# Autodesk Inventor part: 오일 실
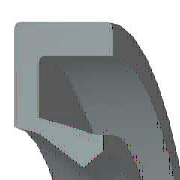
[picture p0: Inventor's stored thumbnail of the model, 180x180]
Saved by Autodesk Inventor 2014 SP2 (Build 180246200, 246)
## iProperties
IsCustomPart: 1
Created: 2012-02
Part Number: 오일 실
Material: 고무
Description: 오일 실 - 스프링 장착, 비스프링, 고무 덮개 G
Document SubType Name: Modeling
Standard: JIS B 2402
Designer: mduedu
Standards Organization: JIS
Language: ko-KR
Size Designation: 20 32 5 A
Categories: <MemberInstance><Categories><Category DisplayName="샤프트 부품" InternalName="7f7aeb1f-a693-4053-b835-cee3144e0d98" Mnemonic="SHFT"><Category DisplayName="실링" Intern
Density: 0.93 g/cm^3
Appearance: 고무 - 검은색 - 버전 1.1
Author: mduedu
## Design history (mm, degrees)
body "Solid1"
revolve "회전1" stored, may be unused: angle "d29" = 360 deg
chamfer "모따기1" distance "d30" = 0.25 (= 0.05 x b); stored, may be unused: second distance "d31" = 0.5 (= 0.1 x b), angle "d39" = 45 deg
chamfer "모따기2" distance "d32" = 0.5 (= 0.1 x b); stored, may be unused: second distance "d33" = 0.25 (= 0.05 x b), angle "d40" = 45 deg
fillet "모깎기1" dims "d34" = 0.25 (= 0.05 x b)
sketch "스케치2"
  geometry: L1 (10.997, -3.438)-(11.297, -5); L2 (10.597, -3.282)-(10.997, -3.438); L3 (10, -1.72)-(10.597, -3.282); L4 (11.091, -1.22)-(10, -1.72); L5 (12.133, -3.75)-(11.091, -1.22); L6 (13.333, -3.75)-(12.133, -3.75); L7 (14.667, -1.25)-(13.333, -3.75); L8 (14.667, 0)-(14.667, -1.25); L9 (16, 0)-(14.667, 0); L10 (16, -5)-(16, 0); L11 (11.297, -5)-(16, -5); L12 (0, -9.6)-(0, 1.6) reference; L13 (28, 0)-(14, 0) reference
  constraints: 22 end point, 3 horizontal, 2 vertical
  dimensions: "d2" = 5 distance of L10.start L9.start (= b); "d4" = 1.25 vertical distance of L5.start L1.end (= 0.25 x b); "d6" = 1.33333 distance of L9.start L8.start (= 0.111111 x dd - 0.111111 x Diam); "d8" = 1.25 distance of L8.start L7.start (= 0.25 x b); "d10" = 1.33333 horizontal distance of L7.start L6.start (= 0.111111 x dd - 0.111111 x Diam); "d12" = 1.21951 vertical distance of L9.start L4.start (= 0.243902 x b); "d14" = 1.09091 horizontal distance of L4.start L3.start (= 0.0909091 x dd - 0.0909091 x Diam); "d16" = 0.5 vertical distance of L4.start L3.start (= 0.1 x b); "d18" = 1.2 distance of L6.start L5.start (= 0.1 x dd - 0.1 x Diam); "d20" = 1.5625 vertical distance of L3.start L2.start (= 0.3125 x b); "d22" = 0.59701 horizontal distance of L3.start L2.start (= 0.0497512 x dd - 0.0497512 x Diam); "d24" = 0.3 horizontal distance of L1.start L1.end (= 0.025 x dd - 0.025 x Diam); "d26" = 1.5625 vertical distance of L1.start L1.end (= 0.3125 x b); "d28" = 0.4 horizontal distance of L2.start L1.start (= 0.0333333 x dd - 0.0333333 x Diam); "d35" = 0 distance between parallel lines of L13 L9; "d36" = 16 distance between parallel lines of L12 L10 (= 0.5 x dd); "d37" = 10 distance from line of L12 L3.start (= 0.5 x Diam)
other parameters: "dd" = 32 [user parameter; used in 8 equation terms], "b" = 5 [user parameter; used in 12 equation terms], "d1" = 8 (derived), "d3" = 2 (derived), "d5" = 2.22222 (derived), "d7" = 2 (derived), "d9" = 2.22222 (derived), "d11" = 1.95122 (derived), "d13" = 1.81818 (derived), "d15" = 0.8 (derived), "d17" = 2 (derived), "d19" = 2.5 (derived), "d21" = 0.99502 (derived), "d23" = 0.5 (derived), "d25" = 2.5 (derived), "d27" = 0.66667 (derived), "d38" = 0
